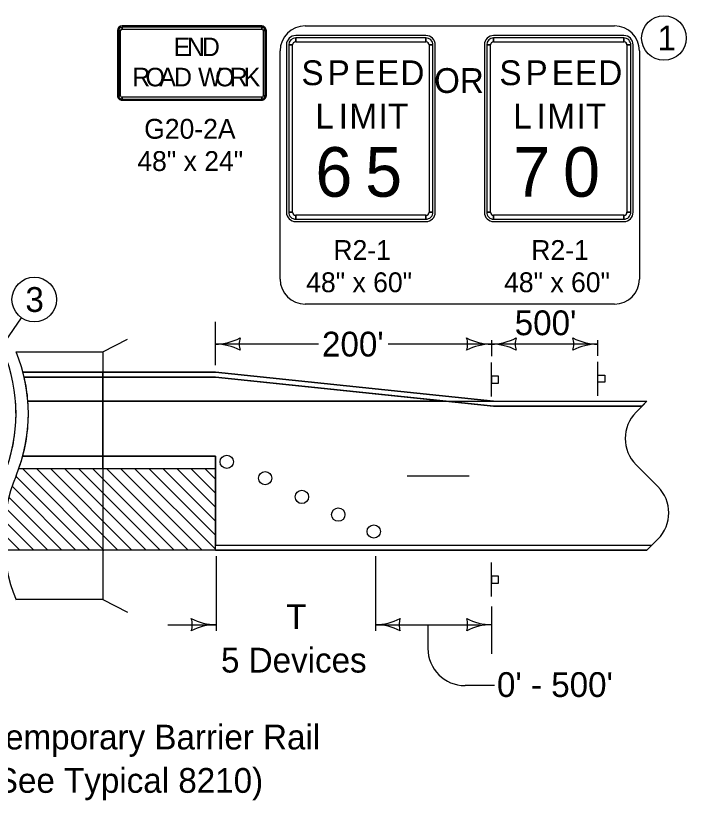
# Model space of a CAD drawing. Extents: x 10133 to 2270741, y 5363 to 1733450.
# Drawn here: x 30684 to 31225, y 6474 to 7107 of the extents above; entities that cross this region are included whole.
import ezdxf

# ---------------------------------------------------------------- set-up
doc = ezdxf.new("R2010")
doc.units = 0
for name, color, linetype in [('dsnNonPlotable', 7, 'Continuous'), ('dsnShtPlotShapeBatchPrint', 7, 'Continuous'), ('dsnStdBorder', 7, 'Continuous'), ('dsnStdLabel', 7, 'Continuous'), ('Level 12', 7, 'Continuous'), ('Level 2', 7, 'Continuous')]:
    doc.layers.add(name, color=color, linetype=linetype)

msp = doc.modelspace()

# ---------------------------------------------------------------- linework, layer by layer
at = {"layer": 'dsnNonPlotable'}
for p, q in [((30754.24, 6835.83), (30774.24, 6845.83)), ((30684.24, 6835.83), (30754.24, 6835.83)), ((30690.85, 6815.33), (30845.01, 6815.33)), ((30845.01, 6815.33), (31069.21, 6791.83)), ((30693.86, 6795.82), (31069.22, 6795.82)), ((31193.06, 6795.83), (31184.27, 6787.04)), ((30845.01, 6751.56), (30689.65, 6751.56)), ((30845.01, 6741.56), (30845.01, 6751.56)), ((30686.48, 6741.56), (30845.01, 6741.56)), ((31184.27, 6744.61), (31201.84, 6727.04)), ((31201.84, 6684.61), (31193.06, 6675.83)), ((30754.24, 6635.83), (30774.24, 6625.83))]:
    msp.add_line(p, q, dxfattribs=at)
for points in [[(30754.24, 6835.83), (30754.24, 6635.83), (30684.24, 6635.83)], [(31069.21, 6791.83), (31189.06, 6791.83)], [(30702.71, 6751.56), (30689.65, 6751.56)], [(30686.48, 6741.56), (30699.54, 6741.56)], [(30999.67, 6735.83), (31049.67, 6735.83)], [(30845.01, 6679.83), (31197.06, 6679.83)]]:
    msp.add_lwpolyline(points, dxfattribs=at)
for centre, radius, start, end in [((30554.24, 6785.82), 130, 337.38013, 22.61986), ((30564.24, 6785.83), 130, 337.38013, 22.61986), ((31205.49, 6765.82), 30, 135, 225), ((30804.24, 6685.82), 130, 157.38013, 202.61986), ((31180.63, 6705.82), 30, 315, 45)]:
    msp.add_arc(centre, radius, start, end, dxfattribs=at)
at = {"layer": 'dsnShtPlotShapeBatchPrint'}
for centre in [(31206.78, 7088.89), (30698.96, 6877.94)]:
    msp.add_circle(centre, 18, dxfattribs=at)
at = {"layer": 'dsnStdBorder'}
for p, q in [((30882.37, 7098.63), (30769.87, 7098.63)), ((30769.87, 7096.13), (30769.87, 7097.69)), ((30882.37, 7097.69), (30882.37, 7096.13)), ((30766.12, 7094.88), (30766.12, 7042.38)), ((30767.06, 7094.88), (30768.62, 7094.88)), ((30883.62, 7094.88), (30885.18, 7094.88)), ((30886.12, 7042.38), (30886.12, 7094.88)), ((31014.83, 7090.86), (30909.83, 7090.86)), ((30909.83, 7085.86), (30909.83, 7088.98)), ((31014.83, 7088.98), (31014.83, 7085.86)), ((31174.42, 7090.86), (31069.42, 7090.86)), ((31069.42, 7085.86), (31069.42, 7088.98)), ((31174.42, 7088.98), (31174.42, 7085.86)), ((30902.33, 7083.36), (30902.33, 6948.36)), ((30904.2, 7083.36), (30907.33, 7083.36)), ((31017.33, 7083.36), (31020.45, 7083.36)), ((31022.33, 6948.36), (31022.33, 7083.36)), ((31061.92, 7083.36), (31061.92, 6948.36)), ((31063.8, 7083.36), (31066.92, 7083.36)), ((31176.92, 7083.36), (31180.05, 7083.36)), ((31181.92, 6948.36), (31181.92, 7083.36)), ((30768.62, 7042.38), (30767.06, 7042.38)), ((30769.87, 7039.57), (30769.87, 7041.13)), ((30769.87, 7038.63), (30882.37, 7038.63)), ((30882.37, 7041.13), (30882.37, 7039.57)), ((30885.18, 7042.38), (30883.62, 7042.38)), ((30907.33, 6948.36), (30904.2, 6948.36)), ((30909.83, 6942.73), (30909.83, 6945.86)), ((31014.83, 6945.86), (31014.83, 6942.73)), ((31020.45, 6948.36), (31017.33, 6948.36)), ((31066.92, 6948.36), (31063.8, 6948.36)), ((31069.42, 6942.73), (31069.42, 6945.86)), ((31174.42, 6945.86), (31174.42, 6942.73)), ((31180.05, 6948.36), (31176.92, 6948.36)), ((30909.83, 6940.86), (31014.83, 6940.86)), ((31069.42, 6940.86), (31174.42, 6940.86)), ((31067.62, 6799.73), (31067.62, 6827.23)), ((31153.27, 6827.71), (31153.27, 6800.21)), ((30845.01, 6815.33), (31069.21, 6791.83)), ((31069.21, 6791.83), (31189.06, 6791.83)), ((30702.71, 6751.56), (30689.65, 6751.56)), ((30754.24, 6751.56), (30702.71, 6751.56)), ((30845.01, 6751.56), (30754.24, 6751.56)), ((30754.24, 6751.56), (30754.24, 6741.56)), ((30754.24, 6741.56), (30754.24, 6751.56)), ((30845.01, 6741.56), (30845.01, 6751.56)), ((30686.48, 6741.56), (30699.54, 6741.56)), ((30689.41, 6741.56), (30755.14, 6675.83)), ((30699.54, 6741.56), (30754.24, 6741.56)), ((30700.72, 6741.56), (30766.45, 6675.83)), ((30712.03, 6741.56), (30777.77, 6675.83)), ((30723.35, 6741.56), (30789.08, 6675.83)), ((30734.66, 6741.56), (30800.4, 6675.83)), ((30745.97, 6741.56), (30811.71, 6675.83)), ((30754.24, 6741.56), (30845.01, 6741.56)), ((30757.29, 6741.56), (30823.02, 6675.83)), ((30768.6, 6741.56), (30834.34, 6675.83)), ((30779.92, 6741.56), (30845.01, 6676.47)), ((30791.23, 6741.56), (30845.01, 6687.78)), ((30802.54, 6741.56), (30845.01, 6699.1)), ((30813.86, 6741.56), (30845.01, 6710.41)), ((30825.17, 6741.56), (30845.01, 6721.72)), ((30836.48, 6741.56), (30845.01, 6733.04)), ((30845.01, 6675.83), (30845.01, 6741.56)), ((30684.12, 6735.53), (30743.83, 6675.83)), ((30681.04, 6727.3), (30732.51, 6675.83)), ((30678.44, 6718.58), (30721.2, 6675.83)), ((30676.39, 6709.32), (30709.89, 6675.83)), ((30674.96, 6699.44), (30698.57, 6675.83)), ((30674.28, 6688.8), (30687.26, 6675.83)), ((30755.14, 6675.83), (30754.24, 6676.72)), ((30754.24, 6676.72), (30754.24, 6675.83)), ((30754.24, 6675.83), (30755.14, 6675.83)), ((31067.62, 6638.29), (31067.62, 6665.79))]:
    msp.add_line(p, q, dxfattribs=at)
for points in [[(30882.37, 7097.69), (30769.87, 7097.69), (30769.87, 7096.13), (30882.37, 7096.13), (30882.37, 7097.69)], [(30767.06, 7094.88), (30767.06, 7042.38), (30768.62, 7042.38), (30768.62, 7094.88), (30767.06, 7094.88)], [(30885.18, 7042.38), (30885.18, 7094.88), (30883.62, 7094.88), (30883.62, 7042.38), (30885.18, 7042.38)], [(31014.83, 7088.98), (30909.83, 7088.98), (30909.83, 7085.86), (31014.83, 7085.86), (31014.83, 7088.98)], [(31174.42, 7088.98), (31069.42, 7088.98), (31069.42, 7085.86), (31174.42, 7085.86), (31174.42, 7088.98)], [(30904.2, 7083.36), (30904.2, 6948.36), (30907.33, 6948.36), (30907.33, 7083.36), (30904.2, 7083.36)], [(31020.45, 6948.36), (31020.45, 7083.36), (31017.33, 7083.36), (31017.33, 6948.36), (31020.45, 6948.36)], [(31063.8, 7083.36), (31063.8, 6948.36), (31066.92, 6948.36), (31066.92, 7083.36), (31063.8, 7083.36)], [(31180.05, 6948.36), (31180.05, 7083.36), (31176.92, 7083.36), (31176.92, 6948.36), (31180.05, 6948.36)], [(30769.87, 7039.57), (30882.37, 7039.57), (30882.37, 7041.13), (30769.87, 7041.13), (30769.87, 7039.57)], [(30909.83, 6942.73), (31014.83, 6942.73), (31014.83, 6945.86), (30909.83, 6945.86), (30909.83, 6942.73)], [(31069.42, 6942.73), (31174.42, 6942.73), (31174.42, 6945.86), (31069.42, 6945.86), (31069.42, 6942.73)], [(31153.36, 6811.26), (31153.36, 6816.88), (31158.99, 6816.88), (31158.99, 6811.26)], [(31067.71, 6816.18), (31067.71, 6810.56), (31073.34, 6810.56), (31073.34, 6816.18)], [(31067.71, 6654.74), (31067.71, 6649.11), (31073.34, 6649.11), (31073.34, 6654.74)]]:
    msp.add_lwpolyline(points, close=True, dxfattribs=at)
for points in [[(30917.33, 7098.63), (31166.92, 7098.63)], [(30897.22, 6894.34), (30897.22, 7078.53)], [(31187.03, 7078.53), (31187.03, 6894.34)], [(31166.92, 6874.24), (30917.33, 6874.24)]]:
    msp.add_lwpolyline(points, dxfattribs=at)
for centre in [(30854.23, 6747.03), (30854.23, 6747.03), (30885.19, 6733.81), (30885.19, 6733.81), (30914.81, 6718.71), (30914.81, 6718.71), (30944.14, 6704.4), (30944.14, 6704.4), (30972.73, 6690.79), (30972.73, 6690.79)]:
    msp.add_circle(centre, 5.37, dxfattribs=at)
for centre, radius, start, end in [((30769.87, 7094.88), 3.75, 90.00021, 179.99985), ((30769.87, 7094.88), 2.81, 90.00021, 179.99985), ((30769.87, 7094.88), 1.25, 90.00021, 179.99985), ((30882.37, 7094.88), 3.75, 0, 90.00021), ((30882.37, 7094.88), 2.81, 0, 90.00021), ((30882.37, 7094.88), 1.25, 0, 90.00021), ((30917.33, 7078.53), 20.1, 90, 180), ((31166.92, 7078.53), 20.1, 0, 90), ((30909.83, 7083.36), 7.5, 90.00021, 179.99985), ((30909.83, 7083.36), 5.62, 90.00021, 179.99985), ((31014.83, 7083.36), 7.5, 0, 90.00021), ((31014.83, 7083.36), 5.62, 0, 90.00021), ((31069.42, 7083.36), 7.5, 90.00021, 179.99985), ((31069.42, 7083.36), 5.62, 90.00021, 179.99985), ((31174.42, 7083.36), 7.5, 0, 90.00021), ((31174.42, 7083.36), 5.62, 0, 90.00021), ((30909.83, 7083.36), 2.5, 90.00021, 179.99985), ((31014.83, 7083.36), 2.5, 0, 90.00021), ((31069.42, 7083.36), 2.5, 90.00021, 179.99985), ((31174.42, 7083.36), 2.5, 0, 90.00021), ((30769.87, 7042.38), 3.75, 179.99985, 270.00006), ((30769.87, 7042.38), 2.81, 179.99985, 270.00006), ((30769.87, 7042.38), 1.25, 179.99985, 270.00006), ((30882.37, 7042.38), 3.75, 270.00006, 0.00027), ((30882.37, 7042.38), 2.81, 270.00006, 0.00027), ((30882.37, 7042.38), 1.25, 270.00006, 0.00027), ((30909.83, 6948.36), 7.5, 179.99985, 270.00006), ((30909.83, 6948.36), 5.62, 179.99985, 270.00006), ((30909.83, 6948.36), 2.5, 179.99985, 270.00006), ((31014.83, 6948.36), 7.5, 270.00006, 0.00027), ((31014.83, 6948.36), 5.62, 270.00006, 0.00027), ((31014.83, 6948.36), 2.5, 270.00006, 0.00027), ((31069.42, 6948.36), 7.5, 179.99985, 270.00006), ((31069.42, 6948.36), 5.62, 179.99985, 270.00006), ((31069.42, 6948.36), 2.5, 179.99985, 270.00006), ((31174.42, 6948.36), 7.5, 270.00006, 0.00027), ((31174.42, 6948.36), 5.62, 270.00006, 0.00027), ((31174.42, 6948.36), 2.5, 270.00006, 0.00027), ((30917.33, 6894.34), 20.1, 180, 270), ((31166.92, 6894.34), 20.1, 270, 0), ((30845.01, 6884.47), 42.5, 270, 298.07249), ((30845.01, 6799.47), 42.5, 61.92751, 90), ((30880.64, 6841.97), 16.42, 162.26665, 197.73335), ((31031.98, 6841.97), 16.42, 342.26665, 17.73335), ((31067.62, 6884.47), 42.5, 241.92751, 270), ((31067.62, 6799.47), 42.5, 90, 118.07249), ((31067.62, 6884.47), 42.5, 270, 298.07249), ((31067.62, 6799.47), 42.5, 61.92751, 90), ((31103.25, 6841.97), 16.42, 162.26665, 197.73335), ((31117.63, 6841.97), 16.42, 342.26665, 17.73335), ((31153.27, 6884.47), 42.5, 241.92751, 270), ((31153.27, 6799.47), 42.5, 90, 118.07249), ((30564.24, 6785.83), 130, 340.09183, 344.71678)]:
    msp.add_arc(centre, radius, start, end, dxfattribs=at)
at = {"layer": 'dsnStdLabel'}
for p, q in [((31067.62, 6845.28), (31067.62, 6832.33)), ((31153.27, 6841.97), (31067.62, 6841.97)), ((31153.27, 6845.28), (31153.27, 6832.6))]:
    msp.add_line(p, q, dxfattribs=at)
at = {"layer": 'Level 12'}
for p, q in [((30595.66, 6728.83), (30688.68, 6863.16)), ((30845.01, 6824.99), (30845.01, 6859.94)), ((30928.14, 6841.97), (30845.01, 6841.97)), ((31067.62, 6841.97), (30984.45, 6841.97)), ((30845.54, 6670.78), (30845.54, 6610.59)), ((30974.03, 6670.78), (30974.03, 6610.59)), ((31067.62, 6630.29), (31067.62, 6592.25)), ((30806.75, 6615.61), (30845.6, 6615.61)), ((30974.03, 6615.61), (31058.75, 6615.61)), ((31016.39, 6615.61), (31016.39, 6596.51)), ((31070, 6566.51), (31046.39, 6566.51))]:
    msp.add_line(p, q, dxfattribs=at)
for centre, radius, start, end in [((30809.96, 6615.61), 16.42, 342.26665, 17.73335), ((30845.6, 6658.11), 42.5, 241.92751, 270), ((30973.97, 6658.11), 42.5, 270, 298.07249), ((31009.61, 6615.61), 16.42, 162.26665, 197.73335), ((31032.05, 6615.61), 16.42, 342.26665, 17.73335), ((31067.69, 6658.11), 42.5, 241.92751, 270), ((30845.6, 6573.11), 42.5, 90, 118.07249), ((30973.97, 6573.11), 42.5, 61.92751, 90), ((31067.69, 6573.11), 42.5, 90, 118.07249), ((31046.39, 6596.51), 30, 180, 270)]:
    msp.add_arc(centre, radius, start, end, dxfattribs=at)
at = {"layer": 'Level 2'}
for p, q in [((30754.24, 6819.33), (30689.85, 6819.33)), ((30689.88, 6819.33), (30845.01, 6819.33)), ((30689.88, 6819.33), (30702.92, 6819.33)), ((30845.01, 6819.33), (30754.24, 6819.33)), ((30754.24, 6819.33), (30754.24, 6815.33)), ((30754.24, 6815.33), (30754.24, 6819.33)), ((30845.01, 6819.33), (31069.21, 6795.83)), ((31069.21, 6795.83), (30845.01, 6819.33)), ((30690.85, 6815.33), (30703.92, 6815.33)), ((30703.92, 6815.33), (30754.24, 6815.33)), ((30754.24, 6815.33), (30845.01, 6815.33)), ((30845.01, 6815.33), (30754.24, 6815.33)), ((30754.24, 6815.33), (30754.24, 6795.82)), ((30754.24, 6795.82), (30754.24, 6815.33)), ((30845.01, 6815.33), (31031.05, 6795.83)), ((31031.05, 6795.83), (30845.01, 6815.33)), ((30754.24, 6795.82), (30693.86, 6795.82)), ((30693.86, 6795.82), (30754.24, 6795.82)), ((30754.24, 6795.82), (30987.4, 6795.82)), ((30754.24, 6751.56), (30754.24, 6795.82)), ((30754.24, 6795.82), (30754.24, 6751.56)), ((30987.4, 6795.83), (31193.06, 6795.83)), ((30987.4, 6795.83), (31031.05, 6795.83)), ((31031.05, 6795.83), (31069.21, 6795.83)), ((31069.21, 6791.83), (31031.05, 6795.82)), ((31069.21, 6791.83), (31031.06, 6795.82)), ((31031.06, 6795.82), (31069.22, 6795.82)), ((31189.06, 6791.83), (31069.21, 6791.83)), ((31189.06, 6791.83), (31069.21, 6791.83)), ((31069.22, 6795.83), (31193.06, 6795.83)), ((31184.27, 6787.04), (31189.06, 6791.82)), ((31193.06, 6795.83), (31189.06, 6791.82)), ((30689.65, 6751.56), (30702.71, 6751.56)), ((30702.71, 6751.56), (30754.24, 6751.56)), ((30754.24, 6751.56), (30845.01, 6751.56)), ((30845.01, 6751.56), (30845.01, 6741.56)), ((30845.01, 6741.56), (30845.01, 6735.83)), ((31201.85, 6727.04), (31184.27, 6744.61)), ((30845.01, 6735.83), (30845.01, 6733.04)), ((30845.01, 6733.04), (30845.01, 6721.72)), ((30845.01, 6721.72), (30845.01, 6710.41)), ((30845.01, 6687.78), (30845.01, 6679.83)), ((31197.06, 6679.82), (31201.85, 6684.61)), ((30845.01, 6679.83), (31197.06, 6679.83)), ((30845.01, 6679.83), (31197.06, 6679.83)), ((31197.06, 6679.82), (31193.06, 6675.83)), ((30845.01, 6675.83), (30674.63, 6675.83)), ((31193.06, 6675.83), (30845.01, 6675.83)), ((30845.01, 6675.83), (31193.06, 6675.83))]:
    msp.add_line(p, q, dxfattribs=at)
for points in [[(30754.24, 6815.33), (30703.92, 6815.33), (30690.85, 6815.33)], [(31031.05, 6795.82), (30987.4, 6795.82), (30754.24, 6795.82)], [(30987.4, 6795.82), (30987.4, 6795.83)], [(31069.22, 6795.82), (31069.22, 6795.83)], [(31189.06, 6791.82), (31189.06, 6791.83)], [(31189.06, 6791.82), (31189.06, 6791.83)], [(30845.01, 6710.41), (30845.01, 6699.1), (30845.01, 6687.78)], [(30845.01, 6675.83), (30845.01, 6676.47), (30845.01, 6679.83)], [(31197.06, 6679.83), (31197.06, 6679.82)], [(31197.06, 6679.83), (31197.06, 6679.82)]]:
    msp.add_lwpolyline(points, dxfattribs=at)
for centre, radius, start, end in [((30564.24, 6785.83), 130, 13.11745, 14.93465), ((30564.24, 6785.83), 130, 4.41084, 13.11745), ((30554.24, 6785.82), 130, 344.71769, 4.41173), ((30564.24, 6785.83), 130, 344.71678, 4.41084), ((31205.49, 6765.82), 30, 135, 225), ((31180.63, 6705.82), 30, 315, 45)]:
    msp.add_arc(centre, radius, start, end, dxfattribs=at)

# ---------------------------------------------------------------- texts
at = {"layer": 'dsnShtPlotShapeBatchPrint'}
for s, p in [('1', (31201.59, 7078.89)), ('3', (30691.82, 6867.94))]:
    msp.add_text(s, height=20, dxfattribs=at).set_placement(p)
at = {"layer": 'dsnStdBorder'}
for s, height, p in [('E', 15, (30811.45, 7074.25)), ('N', 15, (30822.07, 7074.25)), ('D', 15, (30834.15, 7074.25)), ('S', 20, (30914.45, 7050.86)), ('P', 20, (30935.55, 7050.86)), ('E', 20, (30956.64, 7050.86)), ('E', 20, (30975.45, 7050.86)), ('D', 20, (30994.26, 7050.86)), ('S', 20, (31074.05, 7050.86)), ('P', 20, (31095.14, 7050.86)), ('E', 20, (31116.23, 7050.86)), ('E', 20, (31135.04, 7050.86)), ('D', 20, (31153.85, 7050.86)), ('R', 15, (30777.98, 7049.88)), ('O', 15, (30788.67, 7049.88)), ('A', 15, (30799.82, 7049.88)), ('D', 15, (30811.68, 7049.88)), ('W', 15, (30831.13, 7049.88)), ('O', 15, (30844.87, 7049.88)), ('R', 15, (30856.63, 7049.88)), ('K', 15, (30867.93, 7049.88)), ('OR', 20, (31021.35, 7044.58)), ('L', 20, (30925.7, 7015.86)), ('I', 20, (30944.51, 7015.86)), ('M', 20, (30953.11, 7015.86)), ('I', 20, (30976.7, 7015.86)), ('T', 20, (30984.26, 7015.86)), ('L', 20, (31085.3, 7015.86)), ('I', 20, (31104.11, 7015.86)), ('M', 20, (31112.7, 7015.86)), ('I', 20, (31136.29, 7015.86)), ('T', 20, (31143.85, 7015.86)), ('G20-2A', 16, (30787.59, 7007.63)), ('6', 40, (30925.7, 6960.86)), ('5', 40, (30965.82, 6960.86)), ('7', 40, (31085.3, 6960.86)), ('0', 40, (31125.42, 6960.86)), ('48" x 24"', 16, (30782.05, 6981.63)), ('R2-1', 16, (30940.16, 6909.86)), ('R2-1', 16, (31099.76, 6909.86)), ('48" x 60"', 16, (30918.26, 6883.86)), ('48" x 60"', 16, (31077.85, 6883.86))]:
    msp.add_text(s, height=height, dxfattribs=at).set_placement(p)
at = {"layer": 'dsnStdLabel'}
for s, p in [("500'", (31086.41, 6849.15)), ("200'", (30931, 6831.97))]:
    msp.add_text(s, height=20, dxfattribs=at).set_placement(p)
at = {"layer": 'Level 12'}
for s, p in [('T', (30902.12, 6612.04)), ('5 Devices', (30849.57, 6577.04)), ("0' - 500'", (31072.1, 6557.32)), ('Temporary Barrier Rail', (30659.08, 6515.01)), ('(See Typical 8210)', (30659.08, 6480.01))]:
    msp.add_text(s, height=20, dxfattribs=at).set_placement(p)

doc.saveas('drawing.dxf')
